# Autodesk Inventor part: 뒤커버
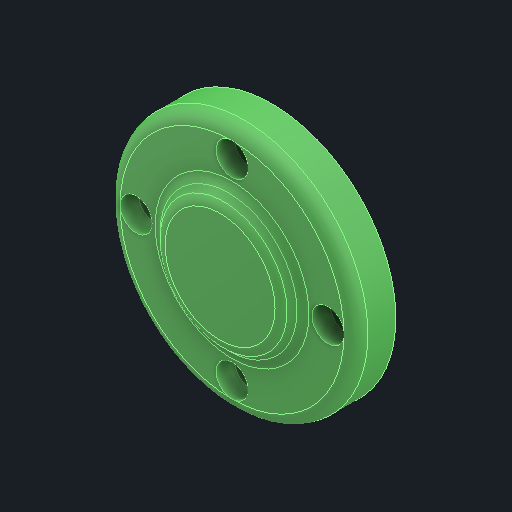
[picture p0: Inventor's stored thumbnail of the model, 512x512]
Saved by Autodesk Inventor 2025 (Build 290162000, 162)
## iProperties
Created: 2025-08
Part Number: 뒤커버
Material: 알루미늄 6061
Document SubType Name: Modeling
Designer: infra002
Density: 2.71 g/cm^3
Appearance: 기본값
Author: jhkim
Sending System: Autodesk Inventor 2026
Preprocessor: ST-DEVELOPER v20.1
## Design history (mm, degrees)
feature "솔리드1"
node "솔리드2"
